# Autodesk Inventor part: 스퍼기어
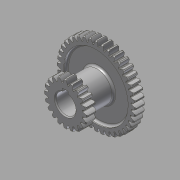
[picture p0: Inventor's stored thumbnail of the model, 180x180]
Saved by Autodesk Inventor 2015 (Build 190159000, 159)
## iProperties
Created: 2015-09
Part Number: 스퍼기어
Material: 강철, 연강
Document SubType Name: Modeling
Designer: mduedu
Density: 7.86 g/cm^3
Mass: 345.726 g
Surface Area: 225.641 cm^2
Volume: 43.9855 cm^3
Appearance: 강철
Author: mduedu
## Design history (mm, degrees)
sketch "스케치1"
  geometry: C1 r 38 at (0, 0); C2 r 40 at (0, 0); C3 r 35.5 at (0, 0); 1 further point
  constraints: 3 centre point, 3 coincident
  dimensions: "d0" = 76 diameter of C1; "d2" = 2 radial gap between concentric circles of C2 C1; "d3" = 71 diameter of C3 (computed from d0)
extrude "돌출1" new body sketch "스케치1" stored distance "d4" = 10; taper "d5" = 0 deg
sketch "스케치2"
  geometry: L1 (0, 35.5)-(0, -35.5); L2 (0, 0)-(40, 0); L3 (0, 0.57)-(39.996, 0.57); L4 (0, 1.57)-(39.969, 1.57); L5 (0, 2.07)-(39.946, 2.07); A1 r 35.5 centre (0, 0) between (0, 35.5) and (0, -35.5) reference; A2 r 40 centre (0, 0) between (40, 0) and (39.946, 2.07) reference; A3 r 9.234 centre (34.93, -7.149) between (39.996, 0.57) and (35.44, 2.07); A4 r 9.234 centre (34.93, 7.149) between (35.44, -2.07) and (39.996, -0.57); A5 r 40 centre (0, 0) between (39.996, -0.57) and (39.996, 0.57); A6 r 35.5 centre (0, 0) between (35.44, -2.07) and (35.44, 2.07); 4 further points
  constraints: 16 point on circle, 10 end point, 6 point on line, 4 centre point, 3 coincident, 3 parallel, 3 symmetric about line, 2 midpoint, 1 perpendicular, 1 vertical, 3 other
  dimensions: "d6" = 0.5 distance between parallel lines of L4 L5; "d8" = 1 distance between parallel lines of L3 L4; "d9" = 1.57 distance between parallel lines of L2 L4
extrude "돌출2" join sketch "스케치2" distance "d10" = 5; taper "d12" = 0 deg; dims "d11" = 5, "d13" = 0
fillet "모깎기1" dims "d17" = 0.5
chamfer "모따기1" distance "d21" = 1; stored, may be unused: second distance "d22" = 2, angle "d23" = 45 deg
sketch "스케치3"
  geometry: C1 r 32.5 at (0, 0); C2 r 15 at (0, 0); 1 further point
  constraints: 2 centre point, 2 coincident
  dimensions: "d27" = 65 diameter of C1; "d28" = 30 diameter of C2
extrude "돌출3" cut sketch "스케치3" distance "d29" = 3; taper "d30" = 0 deg
fillet "모깎기2" dims "d31" = 2
node "작업 평면2"
  node "작업 평면1"
sketch "스케치4"
  geometry: C1 r 15 at (0, 0) reference; 1 further point
extrude "돌출4" join sketch "스케치4" stored distance "d34" = 3; taper "d35" = 0 deg
sketch "스케치5"
  geometry: C1 r 17.5 at (0, 0); C2 r 20 at (0, 0); C3 r 22 at (0, 0); 1 further point
  constraints: 3 centre point, 3 coincident
  dimensions: "d36" = 40 diameter of C2; "d38" = 2 radial gap between concentric circles of C2 C3; "d39" = 35 diameter of C1 (= d36 - 2.5 x d38)
extrude "돌출6" join sketch "스케치5" distance "d46" = 10; taper "d47" = 0 deg
sketch "스케치6"
  geometry: L1 (0, 0)-(0, 22); L2 (-17.5, 0)-(17.5, 0); L3 (-0.57, 0)-(-0.57, 21.993); L4 (-1.57, 0)-(-1.57, 21.944); L5 (-2.07, 0)-(-2.07, 21.902); A1 r 22 centre (0, 0) between (0, 22) and (-0.57, 21.993) reference; A2 r 17.5 centre (0, 0) between (-17.5, 0) and (17.5, 0) reference; A3 r 9.431 centre (7.348, 16.868) between (-0.57, 21.993) and (-2.07, 17.377); A4 r 9.431 centre (-7.348, 16.868) between (2.07, 17.377) and (0.57, 21.993); A5 r 17.5 centre (0, 0) between (2.07, 17.377) and (-2.07, 17.377); A6 r 22 centre (0, 0) between (0.57, 21.993) and (-0.57, 21.993); 4 further points
  constraints: 16 point on circle, 10 end point, 5 point on line, 4 centre point, 3 coincident, 3 symmetric about line, 2 parallel, 2 perpendicular, 1 midpoint, 1 vertical, 3 other
  dimensions: "d40" = 0.5 distance between parallel lines of L4 L5; "d42" = 1 distance between parallel lines of L3 L4; "d43" = 1.57 distance between parallel lines of L1 L4
extrude "돌출5" join sketch "스케치6" distance "d44" = 10; taper "d45" = 0 deg
fillet "모깎기3" dims "d48" = 0.5
chamfer "모따기2" distance "d49" = 1; stored, may be unused: second distance "d50" = 2, angle "d51" = 45 deg
sketch "스케치7"
  geometry: C1 r 10 at (0, 0); 1 further point
  constraints: 1 centre point, 1 coincident
  dimensions: "d55" = 20 diameter of C1
extrude "돌출7" cut sketch "스케치7" stored distance "d56" = 10; taper "d57" = 0 deg
sketch "스케치8"
  geometry: L1 (-9.539, -3)-(-12.8, -3); L2 (-12.8, -3)-(-12.8, 3); L3 (-12.8, 3)-(-9.539, 3); L4 (-9.539, 3)-(-9.539, -3); A1 r 10 centre (0, 0) between (-9.539, -3) and (-9.539, 3) reference; 2 further points
  constraints: 8 end point, 3 point on circle, 2 parallel, 1 horizontal, 1 horizontal alignment, 1 perpendicular
  dimensions: "d58" = 6 distance of L1.end L2.end; "d60" = 22.8 distance from line of point (10, 0) L2
extrude "돌출8" cut sketch "스케치8" stored distance "d61" = 10; taper "d62" = 0 deg
chamfer "모따기3" distance "d63" = 1; stored, may be unused: second distance "d64" = 2, angle "d65" = 45 deg
fillet "모깎기4" dims "d66" = 2
node "솔리드1"
pattern_circular "원형 패턴3" dims "d25" = 360 deg
mirror "대칭1"
pattern_circular "원형 패턴4" dims "d53" = 360 deg
other parameters: "d32" = 9
